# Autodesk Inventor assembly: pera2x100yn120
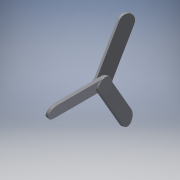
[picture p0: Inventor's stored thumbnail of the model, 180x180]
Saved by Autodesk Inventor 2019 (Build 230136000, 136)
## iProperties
Created: 2020-08
Part Number: pera2x100yn120
Material: 一般
Document SubType Name: Assembly
Designer: kikut
Author: kikut
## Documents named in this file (2)
- F:\openFOAM\bathrobo\bathrobo00\oversetmeshpera2\CAD\pera2x100yn120.iam
- F:\openFOAM\bathrobo\bathrobo00\oversetmeshpera2\CAD\pera02.ipt
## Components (1 placed, 1 different names)
1. pera02:1 — メイト:1, メイト:2
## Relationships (2: Mate 2)
- メイト:1 [Mate]: pera02:1
- メイト:2 [Mate]: pera02:1
